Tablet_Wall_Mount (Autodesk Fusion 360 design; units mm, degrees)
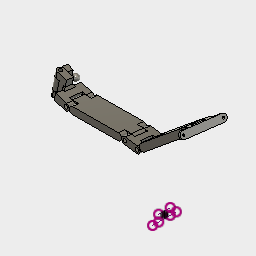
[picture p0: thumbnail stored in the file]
sketch "Arm Body" plane through (0, 0, 0) normal (0, 1, 0) x axis (1, 0, 0)
  line L1 (180, 0) -> (0, 0)
  line L2 (180, 60) -> (180, 0)
  line L3 (0, 60) -> (180, 60)
  line L4 (0, 0) -> (0, 60)
  point P2 (0, 0)
  point P3 (180, 0)
  point P5 (0, 60)
  dimension "d1" distance P2 P3 = 180
  dimension "d2" distance P2 P5 = 60
  dimension "d120" OffsetX = 0
  dimension "d121" OffsetY = 0
  dimension "d122" OffsetZ = 0
  dimension "d123" AngleZ = 0
extrude "Extrude1" new body sketch "Arm Body" along normal blind 17 bodies "Arm"
sketch "Arm Cut" plane through (0, 17, 0) normal (0, 1, 0) x axis (-1, 0, 0)
  line L1 (0, 0) -> (0, -60)
  line L2 (-180, 0) -> (0, 0)
  line L3 (-180, -60) -> (-180, 0)
  line L4 (0, -60) -> (-180, -60)
  line L5 (-162, -44.7) -> (-180, -44.7)
  line L6 (-162, -15.3) -> (-162, -44.7)
  line L7 (-180, -15.3) -> (-162, -15.3)
  line L8 (-180, -44.7) -> (-180, -15.3)
  line L9 (-162, -60) -> (-162, -44.7)
  line L10 (-180, -60) -> (-162, -60)
  line L11 (-180, -44.7) -> (-180, -60)
  line L12 (-162, 0) -> (-162, -15.3)
  line L13 (-180, 0) -> (-162, 0)
  line L14 (-180, -15.3) -> (-180, 0)
  line L15 (-90, 0) -> (-90, -60)
  line L16 (0, -60) -> (-18, -60)
  line L17 (-18, -60) -> (-18, -44.7)
  line L18 (-18, -44.7) -> (0, -44.7)
  line L19 (0, -44.7) -> (0, -60)
  line L20 (-18, -15.3) -> (-18, -44.7)
  line L21 (0, -15.3) -> (-18, -15.3)
  line L22 (0, -44.7) -> (0, -15.3)
  line L23 (0, -15.3) -> (0, 0)
  line L24 (-18, 0) -> (-18, -15.3)
  line L25 (0, 0) -> (-18, 0)
  point P6 (-180, -44.7)
  point P7 (-162, -44.7)
  dimension "d5" distance L4 L5 = 15.3
  dimension "d6" distance L2 L7 = 15.3
  dimension "d7" distance P6 P7 = 18
extrude "Extrude2" sketch "Arm Cut" profile of L1 L2 L3 L4 L5 L7 L9 L10 L11 L12 L13 L14 L16 L17 L18 L19 L21 L23 L24 L25 blind -19
sketch "Arm Holes" plane through (0, 0, -15.3) normal (0, 0, 1) x axis (1, 0, 0)
  line L1 (180, 0) -> (162, 0)
  line L2 (180, 17) -> (180, 0)
  line L3 (162, 17) -> (180, 17)
  line L4 (162, 0) -> (162, 17)
  line L5 (0, 17) -> (0, 0)
  line L6 (18, 17) -> (0, 17)
  line L7 (18, 0) -> (0, 0)
  line L8 (18, 17) -> (162, 17)
  line L9 (162, 0) -> (18, 0)
  line L10 (90, 0) -> (90, 17)
  line L11 (0, 17) -> (8.4725, 17)
  line L12 (0, 0) -> (0, 17)
  line L13 (8.5, 0) -> (0, 0)
  line L14 (180, 17) -> (171.5275, 17)
  line L15 (180, 0) -> (180, 17)
  line L16 (171.5, 0) -> (180, 0)
  circle C1 centre (8.5, 8.5) radius 4.5
  arc A1 centre (8.5, 8.5) radius 8.5 clockwise from (8.5, 0) to (8.4725, 17)
  arc A2 centre (171.5, 8.5) radius 8.5 clockwise from (171.5275, 17) to (171.5, 0)
  circle C2 centre (171.5, 8.5) radius 4.5
  point P6 (8.5, 8.5)
  dimension "d10" diameter C1 = 9
  dimension "d13" distance P6 L5 = 8.5
  dimension "d14" distance P6 L6 = 8.5
extrude "Extrude3" sketch "Arm Holes" profile of C1 C2 blind -30
fillet "Fillet1" radius 8.5
fillet "Fillet2" radius 8.5
fillet "Fillet3" radius 8.5
sketch "Coupler Body" plane through (0, 0, 0) normal (0, 1, 0) x axis (1, 0, 0)
  line L1 (51, 0) -> (0, 0)
  line L2 (51, 60) -> (51, 0)
  line L3 (0, 60) -> (51, 60)
  line L4 (0, 0) -> (0, 60)
  point P2 (0, 0)
  point P3 (51, 0)
  point P5 (0, 60)
  dimension "d21" distance P2 P3 = 51 (= "( 18 * 2 ) * 1 mm + 10 mm + 5 mm")
  dimension "d22" distance P2 P5 = 60
extrude "Extrude1" sketch "Coupler Body" blind 17
sketch "Coupler Cut" plane through (0, 17, 0) normal (0, 1, 0) x axis (-1, 0, 0)
  line L1 (0, 0) -> (0, -60)
  line L2 (-51, 0) -> (0, 0)
  line L3 (-51, -60) -> (-51, 0)
  line L4 (0, -60) -> (-51, -60)
  line L5 (-33, -45) -> (-51, -45)
  line L6 (-33, -15) -> (-33, -45)
  line L7 (-51, -15) -> (-33, -15)
  line L8 (-51, -45) -> (-51, -15)
  line L9 (-25.5, 0) -> (-25.5, -60)
  line L10 (0, -15) -> (-18, -15)
  line L11 (0, -45) -> (0, -15)
  line L12 (-18, -45) -> (0, -45)
  line L13 (-18, -15) -> (-18, -45)
  point P6 (-51, -45)
  point P7 (-33, -45)
  dimension "d25" distance L4 L5 = 15
  dimension "d26" distance L2 L7 = 15
  dimension "d29" distance P6 P7 = 18
extrude "Extrude2" sketch "Coupler Cut" profile of L1 L3 L5 L6 L7 L8 L10 L11 L12 L13 blind -26
sketch "Coupler Holes"
  line L1 (51, 0) -> (0, 0)
  line L2 (51, 17) -> (51, 0)
  line L3 (0, 17) -> (51, 17)
  line L4 (0, 0) -> (0, 17)
  line L5 (25.5, 0) -> (25.5, 17)
  circle C1 centre (42.5, 8.5) radius 4.5
  circle C2 centre (8.5, 8.5) radius 4.5
  point P6 (42.5, 8.5)
  dimension "d30" diameter C1 = 9
  dimension "d31" distance L3 P6 = 8.5
  dimension "d32" distance L2 P6 = 8.5
extrude "Extrude3" sketch "Coupler Holes" profile of C1 C2 blind -65
fillet "Fillet1" radius 9
copy_paste "CopyPaste1"
position "Position1"
ground "Ground1"
ground "Ground2"
ground "Ground3"
joint "Assemble3" alignAngle 0 alignOffsetX 0 alignOffsetY 0 alignOffsetZ 0
joint "Assemble4" alignAngle 0 alignOffsetX 0 alignOffsetY 0 alignOffsetZ 0
position "Position2"
sketch "Mount Body" plane through (0, 0, 0) normal (0, 1, 0) x axis (1, 0, 0)
  line L1 (51, 0) -> (0, 0)
  line L2 (51, 60) -> (51, 0)
  line L3 (0, 60) -> (51, 60)
  line L4 (0, 0) -> (0, 60)
  point P2 (0, 0)
  point P3 (51, 0)
  point P5 (0, 60)
  dimension "d84" distance P2 P3 = 51
  dimension "d85" distance P2 P5 = 60
  dimension "d124" OffsetX = 0
  dimension "d125" OffsetY = 0
  dimension "d126" OffsetZ = 0
  dimension "d127" AngleZ = 0
extrude "Extrude1" sketch "Mount Body" blind 17
sketch "Mount Cut" plane through (0, 17, 0) normal (0, 1, 0) x axis (-1, 0, 0)
  line L1 (0, 0) -> (0, -60)
  line L2 (-51, 0) -> (0, 0)
  line L3 (-51, -60) -> (-51, 0)
  line L4 (0, -60) -> (-51, -60)
  line L5 (-18, -15) -> (0, -15)
  line L6 (-18, -45) -> (-18, -15)
  line L7 (0, -45) -> (-18, -45)
  line L8 (0, -15) -> (0, -45)
  point P7 (0, -45)
  point P9 (-18, -45)
  dimension "d92" distance P7 P9 = 18
  dimension "d93" distance L4 L7 = 15
  dimension "d94" distance L2 L5 = 15
extrude "Extrude2" sketch "Mount Cut" profile of L1 L5 L6 L7 L8 blind -21
sketch "Mount Hole"
  line L1 (51, 0) -> (0, 0)
  line L2 (51, 17) -> (51, 0)
  line L3 (0, 17) -> (51, 17)
  line L4 (0, 0) -> (0, 17)
  circle C1 centre (8.5, 8.5) radius 4.5
  point P6 (8.5, 8.5)
  dimension "d97" diameter C1 = 9
  dimension "d98" distance L3 P6 = 8.5
  dimension "d99" distance L4 P6 = 8.5
extrude "Extrude3" sketch "Mount Hole" profile of C1 blind -68
fillet "Fillet1" radius 8.5
extrude "Extrude4" of existing geometry blind -10 (= "23 mm - 33 mm")
extrude "Extrude5" of existing geometry blind -5
extrude "Extrude6" of existing geometry blind -13
sketch "Wall Extension" plane through (0, 17, 0) normal (0, 1, 0) x axis (-1, 0, 0)
  line L1 (-23, -60) -> (-23, 0)
  line L2 (-8.5, -60) -> (-23, -60)
  line L3 (-8.5, -45) -> (-8.5, -60)
  line L4 (-18, -45) -> (-8.5, -45)
  line L5 (-18, -15) -> (-18, -45)
  line L6 (-8.5, -15) -> (-18, -15)
  line L7 (-8.5, 0) -> (-8.5, -15)
  line L8 (-23, 0) -> (-8.5, 0)
  line L9 (-23, -85) -> (-23, -60)
  line L10 (-28, -85) -> (-23, -85)
  line L11 (-23, 25) -> (-23, 0)
  line L12 (-28, 25) -> (-23, 25)
  line L13 (-28, -85) -> (-28, 25)
  line L14 (-23, -30) -> (-28, -30)
  point P10 (-23, -60)
  point P11 (-23, -85)
  point P13 (-23, 0)
  point P14 (-23, 25)
  point P12 (-28, -85)
  dimension "d111" distance P10 P11 = 25
  dimension "d112" distance P13 P14 = 25
  dimension "d113" distance P11 P12 = 5
extrude "Extrude7" sketch "Wall Extension" profile of L1 L9 L10 L11 L12 L13 blind -17
sketch "Wall Holes" plane through (18, 0, 0) normal (-1, 0, 0) x axis (0, 0, 1)
  line L1 (-15, 0) -> (-45, 0)
  line L2 (-15, 17) -> (-15, 0)
  line L3 (-45, 17) -> (-15, 17)
  line L4 (-45, 0) -> (-45, 17)
  line L5 (-85, 0) -> (-85, 17)
  line L6 (-85, 17) -> (-60, 17)
  line L7 (-30, 0) -> (-30, 17)
  circle C1 centre (-77, 8.5) radius 2.5
  circle C2 centre (17, 8.5) radius 2.5
  point P6 (-77, 8.5)
  dimension "d114" diameter C1 = 5
  dimension "d115" distance P6 L5 = 8
  dimension "d116" distance P6 L6 = 8.5
extrude "Extrude8" cut sketch "Wall Holes" profile of C1 C2 against normal blind 17
fillet "Fillet2" radius 8.5
position "Position3"
ground "Ground4"
ground "Ground5"
joint "Assemble5" alignAngle -90 alignOffsetX 0 alignOffsetY 0 alignOffsetZ 0
position "Position4"
sketch "Holder Body" plane through (0, 0, 0) normal (0, 1, 0) x axis (1, 0, 0)
  line L1 (40, 0) -> (0, 0)
  line L2 (40, 60) -> (40, 0)
  line L3 (0, 60) -> (40, 60)
  line L4 (0, 0) -> (0, 60)
  point P2 (0, 0)
  point P3 (40, 0)
  point P5 (0, 60)
  dimension "d140" distance P2 P3 = 40
  dimension "d141" distance P2 P5 = 60
extrude "Extrude1" sketch "Holder Body" blind 17
sketch "Sketch2" plane through (0, 17, 0) normal (0, 1, 0) x axis (-1, 0, 0)
  line L1 (0, 0) -> (0, -60)
  line L2 (-40, 0) -> (0, 0)
  line L3 (-40, -60) -> (-40, 0)
  line L4 (0, -60) -> (-40, -60)
  line L5 (-18, -45) -> (0, -45)
  line L6 (-18, -15) -> (-18, -45)
  line L7 (0, -15) -> (-18, -15)
  line L8 (0, -45) -> (0, -15)
  point P6 (0, -45)
  point P7 (-18, -45)
  dimension "d147" distance L4 L5 = 15
  dimension "d148" distance L2 L7 = 15
  dimension "d149" distance P6 P7 = 18
extrude "Extrude2" cut sketch "Sketch2" profile of L1 L5 L6 L7 L8 against normal blind 17
sketch "Sketch3"
  line L1 (40, 0) -> (0, 0)
  line L2 (40, 17) -> (40, 0)
  line L3 (0, 17) -> (40, 17)
  line L4 (0, 0) -> (0, 17)
  circle C1 centre (8.5, 8.5) radius 4.5
  point P6 (8.5, 8.5)
  dimension "d153" diameter C1 = 9
  dimension "d154" distance L3 P6 = 8.5
  dimension "d155" distance P6 L4 = 8.5
fillet "Fillet2" radius 8.5
extrude "Extrude3" cut sketch "Sketch3" profile of C1 blind -65
sketch "Sketch4" plane through (40, 0, 0) normal (1, 0, 0) x axis (0, 0, -1)
  line L1 (60, 0) -> (0, 0)
  line L2 (60, 17) -> (60, 0)
  line L3 (0, 17) -> (60, 17)
  line L4 (0, 0) -> (0, 17)
  line L5 (38.5, 38.5) -> (21.5, 38.5)
  line L6 (38.5, -21.5) -> (38.5, 38.5)
  line L7 (21.5, -21.5) -> (38.5, -21.5)
  line L8 (21.5, 38.5) -> (21.5, -21.5)
  line L9 (38.5, 8.5) -> (21.5, 8.5)
  point P6 (21.5, 38.5)
  point P7 (38.5, 38.5)
  point P8 (38.5, -21.5)
  dimension "d159" distance P6 P7 = 17
  dimension "d160" distance L4 L8 = 21.5
  dimension "d161" distance P7 P8 = 60
  dimension "d162" distance L3 L9 = 8.5 (= "( 17 / 2 ) * 1 mm")
extrude "Extrude4" add sketch "Sketch4" profile of L1 L3 L5 L6 L7 L8 along normal blind 35
sketch "Sketch5" plane through (0, 38.5, 0) normal (0, 1, 0) x axis (-1, 0, 0)
  line L1 (-40, -21.5) -> (-40, -38.5)
  line L2 (-75, -21.5) -> (-40, -21.5)
  line L3 (-75, -38.5) -> (-75, -21.5)
  line L4 (-40, -38.5) -> (-75, -38.5)
  circle C1 centre (-66.5, -30) radius 4
  point P6 (-66.5, -30)
  dimension "d165" diameter C1 = 8
  dimension "d166" distance L3 P6 = 8.5
  dimension "d167" distance L4 P6 = 8.5
sketch "Sketch6" plane through (0, 0, -38.5) normal (0, 0, -1) x axis (-1, 0, 0)
  line L1 (-40, 38.5) -> (-40, 17)
  line L2 (-75, 38.5) -> (-40, 38.5)
  line L3 (-75, -21.5) -> (-75, 38.5)
  line L4 (-40, -21.5) -> (-75, -21.5)
  line L5 (-40, 0) -> (-40, -21.5)
  line L6 (-40, 17) -> (-40, 0)
sketch "Sketch7" plane through (0, 0, -21.5) normal (0, 0, 1) x axis (1, 0, 0)
  line L1 (40, -21.5) -> (40, 0)
  line L2 (75, -21.5) -> (40, -21.5)
  line L3 (75, 38.5) -> (75, -21.5)
  line L4 (40, 38.5) -> (75, 38.5)
  line L5 (40, 17) -> (40, 38.5)
  line L6 (40, 0) -> (40, 17)
  line L7 (57, 23.5) -> (75, 23.5)
  line L8 (57, -6.5) -> (57, 23.5)
  line L9 (75, -6.5) -> (57, -6.5)
  line L10 (75, 23.5) -> (75, -6.5)
  line L11 (75, 38.5) -> (40, 38.5)
  point P8 (75, 23.5)
  point P9 (57, 23.5)
  dimension "d168" distance L7 L11 = 15
  dimension "d169" distance L2 L9 = 15
  dimension "d170" distance P8 P9 = 18
extrude "Extrude5" cut sketch "Sketch5" profile of C1 against normal blind 62
fillet "Fillet3" radius 8.5
extrude "Extrude6" cut sketch "Sketch7" profile of L3 L7 L8 L9 L10 against normal blind 37
sketch "Sketch1" plane through (0, 0, 0) normal (0, 1, 0) x axis (1, 0, 0)
  line L1 (30, 0) -> (0, 0)
  line L2 (30, 60) -> (30, 0)
  line L3 (0, 60) -> (30, 60)
  line L4 (0, 0) -> (0, 60)
  point P2 (0, 0)
  point P3 (30, 0)
  point P5 (0, 60)
  dimension "d178" distance P2 P3 = 30
  dimension "d179" distance P2 P5 = 60
extrude "Extrude1" sketch "Sketch1" blind 17
sketch "Sketch2" plane through (0, 17, 0) normal (0, 1, 0) x axis (-1, 0, 0)
  line L1 (0, 0) -> (0, -60)
  line L2 (-30, 0) -> (0, 0)
  line L3 (-30, -60) -> (-30, 0)
  line L4 (0, -60) -> (-30, -60)
  line L5 (-18, -44.7) -> (0, -44.7)
  line L6 (-18, -15.3) -> (-18, -44.7)
  line L7 (0, -15.3) -> (-18, -15.3)
  line L8 (0, -44.7) -> (0, -15.3)
  line L9 (-18, 0) -> (-18, -15.3)
  line L10 (0, 0) -> (-18, 0)
  line L11 (0, -15.3) -> (0, 0)
  line L12 (-18, -60) -> (-18, -44.7)
  line L13 (0, -60) -> (-18, -60)
  line L14 (0, -44.7) -> (0, -60)
  point P6 (0, -44.7)
  point P7 (-18, -44.7)
  dimension "d182" distance P6 P7 = 18
  dimension "d183" distance L4 L5 = 15.3
  dimension "d184" distance L2 L7 = 15.3
sketch "Sketch4"
  line L1 (30, 0) -> (0, 0)
  line L2 (30, 17) -> (30, 0)
  line L3 (0, 17) -> (30, 17)
  line L4 (0, 0) -> (0, 17)
  circle C1 centre (8.5, 8.5) radius 4
  point P6 (8.5, 8.5)
  dimension "d185" diameter C1 = 8
  dimension "d186" distance L3 P6 = 8.5
  dimension "d187" distance L4 P6 = 8.5
extrude "Extrude2" sketch "Sketch4" profile of C1 blind -70
fillet "Fillet1" radius 8.5
sketch "Sketch5" plane through (30, 0, 0) normal (1, 0, 0) x axis (0, 0, -1)
  line L1 (60, 0) -> (0, 0)
  line L2 (60, 17) -> (60, 0)
  line L3 (0, 17) -> (60, 17)
  line L4 (0, 0) -> (0, 17)
  line L5 (30, 0) -> (30, 17)
  line L6 (0, 8.5) -> (60, 8.5)
  circle C1 centre (30, 8.5) radius 5
  dimension "d195" diameter C1 = 10
extrude "Extrude4" add sketch "Sketch5" profile of C1 along normal blind 16
position "Position5"
extrude "Extrude5" sketch "Sketch2" profile of L1 L2 L4 L5 L7 L9 L10 L11 L12 L13 L14 blind -25
sketch "Sketch1" plane through (34.8034, 0, 0) normal (1, 0, 0) x axis (0, 0, -1)
  line L1 (44.9001, 18.8389) -> (15.5001, 18.8389)
  line L2 (15.5001, 1.8389) -> (44.9001, 1.8389)
  line L3 (60.2001, 1.8389) -> (0.2001, 1.8389)
  line L4 (30.2001, 1.8389) -> (30.2001, 18.8389)
  circle C1 centre (30.2001, 10.3389) radius 5
  arc A1 centre (30.2001, 10.3389) radius 8.5 clockwise from (30.2001, 18.8389) to (30.2001, 1.8389)
revolve "Revolve2" sketch "Sketch1" AlongAngle 360
position "Position6"
joint "Assemble6" alignAngle -90 alignOffsetX 0 alignOffsetY 0 alignOffsetZ 0
position "Position7"
joint "Assemble7" alignAngle -90 alignOffsetX 0 alignOffsetY 0 alignOffsetZ 0
chamfer "Chamfer3" distance 5
chamfer "Chamfer4" distance 5
position "Position8"
ground "Ground6"
position "Position9"
ground "Ground7"
ground "Ground8"
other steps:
create_component "CreateComponent1"
create_component "CreateComponent2"
joint_origin "JointOrigin3" OffsetX 0 OffsetY 0 OffsetZ 0 AngleZ 0
joint_origin "JointOrigin3" OffsetX 0 OffsetY 0 OffsetZ 0 AngleZ 0
joint_origin "JointOrigin4" OffsetX 0 OffsetY 0 OffsetZ 0 AngleZ 0
joint_origin "JointOrigin4" OffsetX 0 OffsetY 0 OffsetZ 0 AngleZ 0
create_component "CreateComponent3"
joint_origin "JointOrigin6" OffsetX 0 OffsetY 0 OffsetZ 0 AngleZ 0
joint_origin "JointOrigin2" OffsetX 0 OffsetY 0 OffsetZ 0 AngleZ 0
create_component "CreateComponent4"
create_component "CreateComponent5"
joint_origin "JointOrigin1" OffsetX 0 OffsetY 0 OffsetZ 0 AngleZ 0
joint_origin "JointOrigin7" OffsetX 0 OffsetY 0 OffsetZ 0 AngleZ 0
joint_origin "JointOrigin1" OffsetX 0 OffsetY 0 OffsetZ 0 AngleZ 0
joint_origin "JointOrigin2" OffsetX 0 OffsetY 0 OffsetZ 0 AngleZ 0
named bodies: "Arm"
